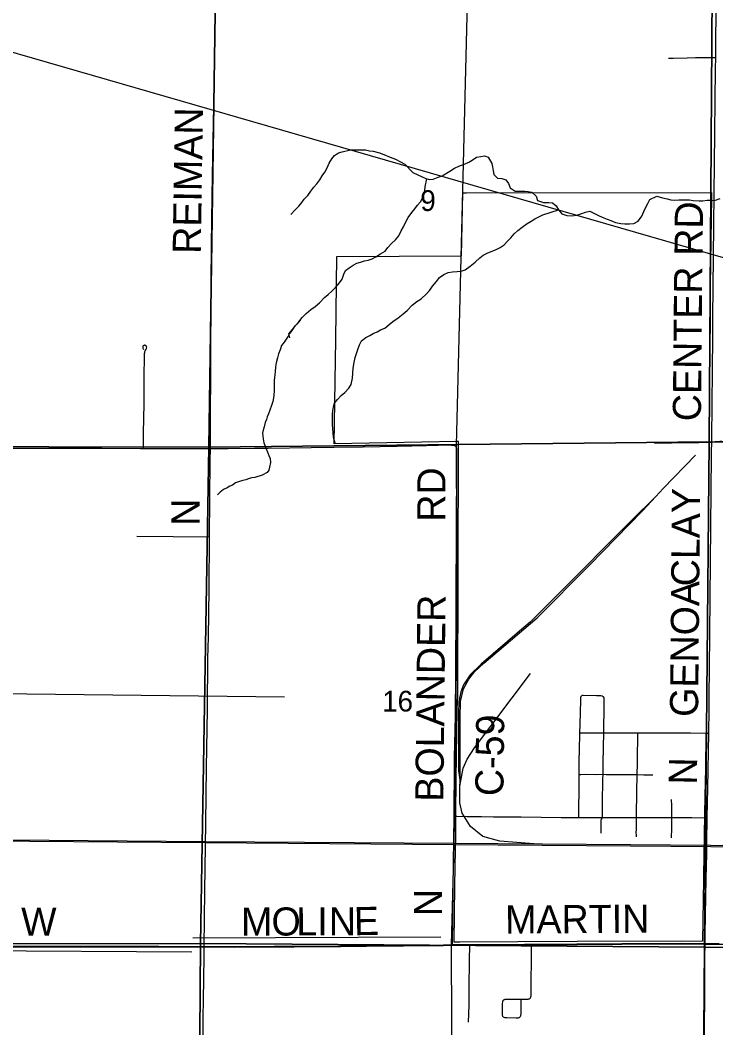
# Model space of a CAD drawing. Extents: x 0 to 34, y 0 to 22.
# Drawn here: x 6.257 to 7.662, y 17.233 to 19.268 of the extents above; entities that cross this region are included whole.
import ezdxf

# ---------------------------------------------------------------- set-up
doc = ezdxf.new("R2010")
doc.units = 0
for name, color, linetype in [('GM_X_City_Street', 7, 'Continuous'), ('GM_X_Corporation', 7, 'Continuous'), ('GM_X_County_Road', 7, 'Continuous'), ('GM_X_County_Road_Text', 7, 'Continuous'), ('GM_X_Interstate_Route', 7, 'Continuous'), ('GM_X_Minor_River', 7, 'Continuous'), ('GM_X_Rail_Line', 7, 'Continuous'), ('GM_X_Section', 7, 'Continuous'), ('GM_X_Section_Text', 7, 'Continuous'), ('GM_X_Township_Road', 7, 'Continuous'), ('GM_X_Township_Road_Text', 7, 'Continuous'), ('SH_Text', 7, 'Continuous')]:
    doc.layers.add(name, color=color, linetype=linetype)

msp = doc.modelspace()

# ---------------------------------------------------------------- linework, layer by layer
at = {"layer": 'GM_X_City_Street'}
for points in [[(7.5379, 18.4138), (7.5471, 18.4143), (7.5718, 18.4148), (7.6271, 18.4153), (7.6462, 18.4158), (7.6532, 18.4161)], [(7.385, 17.6579), (7.3851, 17.667), (7.3853, 17.7216), (7.3855, 17.745), (7.3857, 17.7742), (7.3861, 17.7928), (7.3871, 17.8289), (7.3876, 17.8454), (7.3888, 17.8949), (7.3892, 17.9014), (7.3894, 17.9023), (7.3903, 17.9036), (7.3909, 17.9042)], [(7.3909, 17.9042), (7.3921, 17.9048), (7.3938, 17.9051), (7.4205, 17.9045), (7.4291, 17.9041), (7.4319, 17.9035), (7.434, 17.9023)], [(7.4301, 17.6259), (7.4301, 17.6342), (7.43, 17.6402), (7.43, 17.6489), (7.4302, 17.6524), (7.431, 17.6546), (7.4324, 17.6579), (7.4324, 17.6634), (7.4324, 17.672), (7.4329, 17.6868), (7.4335, 17.7354), (7.4338, 17.7451), (7.4341, 17.7711), (7.4347, 17.7957), (7.435, 17.8077), (7.4352, 17.821), (7.4352, 17.829), (7.4353, 17.8445), (7.436, 17.8706), (7.436, 17.8769), (7.4363, 17.8894), (7.4363, 17.8956), (7.4358, 17.8991), (7.4353, 17.9007), (7.434, 17.9023)], [(7.3871, 17.8289), (7.392, 17.8289), (7.3951, 17.829), (7.4107, 17.8288), (7.4352, 17.829), (7.4606, 17.8288), (7.5042, 17.8289), (7.5137, 17.8289), (7.6106, 17.8287), (7.6418, 17.8285), (7.6472, 17.8285)], [(7.5011, 17.6188), (7.5011, 17.6219), (7.501, 17.6278), (7.5011, 17.6337), (7.5013, 17.6367), (7.5014, 17.6429), (7.5013, 17.658), (7.5014, 17.6605), (7.5015, 17.6708), (7.5017, 17.6739), (7.5016, 17.677), (7.5017, 17.6801), (7.502, 17.6915), (7.5021, 17.7081), (7.5023, 17.7211), (7.5027, 17.7324), (7.503, 17.7445), (7.5033, 17.7667), (7.5034, 17.7829), (7.5037, 17.7948), (7.5039, 17.8069), (7.5042, 17.8195), (7.5042, 17.8289)], [(7.3855, 17.745), (7.389, 17.745), (7.3991, 17.7451), (7.4203, 17.7449), (7.4338, 17.7451), (7.4401, 17.7446), (7.4546, 17.7444), (7.4655, 17.7446), (7.4791, 17.7444), (7.4946, 17.7444), (7.503, 17.7445), (7.5161, 17.7442), (7.5346, 17.7438)], [(7.5723, 17.6169), (7.5724, 17.6355), (7.5727, 17.6579), (7.5727, 17.6634), (7.5726, 17.682), (7.5723, 17.6943)], [(7.1329, 17.6604), (7.1386, 17.6603), (7.1597, 17.6599), (7.1882, 17.6597), (7.2129, 17.6594), (7.2346, 17.6592), (7.2688, 17.6589), (7.3494, 17.658), (7.3774, 17.6579), (7.385, 17.6579), (7.4324, 17.6579), (7.5013, 17.658), (7.5201, 17.6579), (7.5512, 17.6579), (7.5727, 17.6579), (7.6132, 17.6577), (7.6409, 17.6573), (7.6443, 17.6572)]]:
    msp.add_lwpolyline(points, dxfattribs=at)
at = {"layer": 'GM_X_Corporation'}
msp.add_lwpolyline([(7.1415, 18.417), (7.1409, 18.417), (7.1384, 18.4169), (6.9975, 18.4142), (6.891, 18.4123), (6.8941, 18.6234), (6.8966, 18.7909), (7.148, 18.7918), (7.1506, 18.9195), (7.1582, 18.9196), (7.6531, 18.9202), (7.653, 18.9097), (7.6516, 18.8246), (7.6504, 18.7301), (7.6499, 18.6685), (7.6493, 18.6019), (7.6489, 18.544), (7.648, 18.436), (7.6478, 18.4181), (7.6478, 18.4125), (7.6475, 18.3869), (7.6454, 18.1634), (7.643, 17.9082), (7.643, 17.9056), (7.6428, 17.8895), (7.6418, 17.8336), (7.6417, 17.8241), (7.6413, 17.8017), (7.6409, 17.7795), (7.6404, 17.7573), (7.6394, 17.7012), (7.6388, 17.6639), (7.6387, 17.6582), (7.6386, 17.6525), (7.6382, 17.633), (7.6379, 17.6139), (7.6374, 17.5893), (7.6364, 17.5325), (7.6344, 17.4083), (7.3813, 17.4073), (7.2621, 17.4069), (7.1448, 17.4059), (7.1334, 17.4058), (7.1345, 17.5199), (7.1359, 17.5933), (7.1363, 17.6151), (7.1366, 17.6571), (7.1366, 17.6647), (7.1371, 17.7348), (7.1394, 17.8768), (7.1403, 17.9034), (7.1413, 18.1554), (7.1423, 18.4113), (7.1422, 18.417)], close=True, dxfattribs=at)
at = {"layer": 'GM_X_County_Road'}
msp.add_line((7.13, 17.3998), (7.1649, 17.4001), dxfattribs=at)
for points in [[(7.6615, 19.1928), (7.6618, 19.2257), (7.663, 19.3406), (7.6641, 19.424)], [(7.6556, 18.6674), (7.657, 18.7904), (7.6583, 18.918), (7.6589, 18.977), (7.6612, 19.1697), (7.6615, 19.1928)], [(7.6532, 18.4161), (7.6532, 18.4267), (7.6539, 18.4889), (7.6545, 18.5635), (7.6552, 18.6256), (7.6553, 18.6474), (7.6556, 18.6674)], [(7.1329, 17.6604), (7.1331, 17.6793), (7.1336, 17.7476), (7.1341, 17.7787), (7.1357, 17.8625), (7.1368, 17.9526), (7.1368, 17.9836), (7.1367, 18.0054), (7.1372, 18.0271), (7.1372, 18.0395), (7.1376, 18.0985), (7.1376, 18.1172), (7.1379, 18.2228), (7.1386, 18.3905), (7.1385, 18.3987), (7.1384, 18.4013), (7.1383, 18.4024), (7.1381, 18.4042), (7.1378, 18.4051), (7.1376, 18.4058), (7.137, 18.4067)], [(7.6483, 17.9044), (7.6489, 17.9574), (7.653, 18.3894), (7.6531, 18.3962), (7.6532, 18.4161)], [(7.6472, 17.8285), (7.648, 17.8766), (7.6483, 17.9004), (7.6483, 17.9044)], [(7.6443, 17.6572), (7.6443, 17.6592), (7.6448, 17.6871), (7.6454, 17.7181), (7.6472, 17.8285)], [(7.13, 17.3998), (7.1301, 17.4128), (7.1303, 17.447), (7.1312, 17.5275), (7.1318, 17.5523), (7.1316, 17.5678), (7.1325, 17.6112), (7.1329, 17.6604)], [(7.6402, 17.4023), (7.6403, 17.4231), (7.6421, 17.5349), (7.6432, 17.5846), (7.6436, 17.6157), (7.6443, 17.6499), (7.6443, 17.6572)], [(5.8898, 17.4002), (5.9248, 17.3997), (5.9621, 17.3993), (6.0584, 17.3982), (6.1734, 17.397), (6.2324, 17.3969), (6.2728, 17.3967), (6.3195, 17.3967), (6.3599, 17.3969), (6.3971, 17.3968), (6.4904, 17.397), (6.537, 17.3967), (6.6147, 17.3964), (6.6286, 17.3964)], [(6.6286, 17.3964), (6.6893, 17.3963), (6.77, 17.3966), (6.8104, 17.3969), (6.8415, 17.3971), (6.9037, 17.3975), (6.9565, 17.3979), (7.0031, 17.3986), (7.031, 17.3989), (7.1117, 17.3997), (7.13, 17.3998)], [(7.1649, 17.4001), (7.1819, 17.4002), (7.2224, 17.4005), (7.2754, 17.4009), (7.2892, 17.401)], [(7.2892, 17.401), (7.3814, 17.4014), (7.4718, 17.4022), (7.5933, 17.4026), (7.6402, 17.4023)], [(7.6367, 17.065), (7.6366, 17.0726), (7.6373, 17.1192), (7.6377, 17.1626), (7.6387, 17.2186), (7.6392, 17.3115), (7.6396, 17.3767), (7.6402, 17.4023)], [(7.6402, 17.4023), (7.6683, 17.4021), (7.7243, 17.4019), (7.8426, 17.4016), (7.908, 17.4013), (7.9796, 17.4005), (8.0792, 17.3999), (8.1321, 17.399), (8.266, 17.3978), (8.3189, 17.3974), (8.4403, 17.3965), (8.4714, 17.3958), (8.4806, 17.3953), (8.4898, 17.3941), (8.4989, 17.3923), (8.511, 17.3893), (8.5888, 17.3671), (8.6307, 17.3552), (8.6461, 17.3509)]]:
    msp.add_lwpolyline(points, dxfattribs=at)
at = {"layer": 'GM_X_Interstate_Route'}
for points in [[(6.2322, 17.3975), (6.2726, 17.3973), (6.3192, 17.3973), (6.3596, 17.3974), (6.3969, 17.3974), (6.4902, 17.3975), (6.5368, 17.3973), (6.6145, 17.397), (6.6284, 17.397), (6.6891, 17.3968), (6.7698, 17.3972), (6.8102, 17.3975), (6.8413, 17.3976), (6.9034, 17.3981), (6.9563, 17.3985), (7.0029, 17.3992), (7.0308, 17.3994), (7.1114, 17.4002), (7.1298, 17.4004), (7.1647, 17.4006), (7.1817, 17.4007), (7.2222, 17.401), (7.2752, 17.4014), (7.289, 17.4015), (7.3812, 17.402), (7.4715, 17.4028), (7.5931, 17.4031), (7.6399, 17.4028), (7.6681, 17.4026)], [(7.6681, 17.4026), (7.6399, 17.4028), (7.5931, 17.4031), (7.4715, 17.4028), (7.3812, 17.402), (7.289, 17.4015), (7.2752, 17.4014), (7.2222, 17.401), (7.1817, 17.4007), (7.1647, 17.4006), (7.1298, 17.4004), (7.1114, 17.4002), (7.0308, 17.3994), (7.0029, 17.3992), (6.9563, 17.3985), (6.9034, 17.3981), (6.8413, 17.3976), (6.8102, 17.3975), (6.7698, 17.3972), (6.6891, 17.3968), (6.6284, 17.397), (6.6145, 17.397), (6.5368, 17.3973), (6.4902, 17.3975), (6.3969, 17.3974), (6.3596, 17.3974), (6.3192, 17.3973), (6.2726, 17.3973), (6.2322, 17.3975)]]:
    msp.add_lwpolyline(points, dxfattribs=at)
at = {"layer": 'GM_X_Minor_River'}
for points in [[(6.8037, 18.8754), (6.8125, 18.8849), (6.8193, 18.8924), (6.8258, 18.8996), (6.8304, 18.9068), (6.838, 18.9143), (6.8441, 18.923), (6.8502, 18.9306), (6.8559, 18.9378), (6.862, 18.9457), (6.867, 18.9536), (6.872, 18.9608), (6.8769, 18.9699), (6.8808, 18.979), (6.8861, 18.9877), (6.8914, 18.9949), (6.8994, 19.0002), (6.9074, 19.002), (6.9241, 19.0061), (6.9381, 19.0064), (6.9464, 19.0064), (6.9544, 19.006), (6.9623, 19.0044), (6.9695, 19.0032), (6.9828, 19.0001), (6.9911, 18.997), (7.0043, 18.9913), (7.0149, 18.9871), (7.0247, 18.9817), (7.0334, 18.9771), (7.0496, 18.9607), (7.0599, 18.9557), (7.0674, 18.9526), (7.0757, 18.948), (7.0829, 18.9461), (7.0905, 18.9472), (7.1011, 18.951), (7.1091, 18.954), (7.1243, 18.9634), (7.1342, 18.969), (7.1425, 18.9731), (7.1554, 18.978), (7.1627, 18.981), (7.1699, 18.9855), (7.1782, 18.9912), (7.1873, 18.993), (7.1945, 18.9941), (7.2017, 18.9914), (7.2096, 18.9789), (7.2107, 18.9717), (7.2118, 18.9637), (7.2133, 18.9561), (7.2205, 18.9488), (7.2292, 18.948), (7.2375, 18.9457), (7.2431, 18.9381), (7.2461, 18.9297), (7.2563, 18.9229), (7.2643, 18.9228), (7.2757, 18.9228), (7.2829, 18.9223), (7.29, 18.9208), (7.2991, 18.9128), (7.3017, 18.904), (7.3138, 18.8998), (7.3244, 18.8998), (7.3316, 18.899), (7.3392, 18.8928), (7.344, 18.8852), (7.3508, 18.8769), (7.3607, 18.8738), (7.3705, 18.873), (7.3811, 18.8744), (7.391, 18.8774), (7.3982, 18.8804), (7.4073, 18.8823), (7.4164, 18.8773), (7.4247, 18.8734), (7.4323, 18.87), (7.4421, 18.8665), (7.4493, 18.8635), (7.4591, 18.8592), (7.4697, 18.8573), (7.478, 18.8565), (7.4875, 18.8568), (7.4958, 18.8575), (7.5046, 18.862), (7.5122, 18.8723), (7.5164, 18.8817), (7.5195, 18.8893), (7.5245, 18.898), (7.5283, 18.9056), (7.5423, 18.9123), (7.5537, 18.9092), (7.5635, 18.9069), (7.5707, 18.9054), (7.5779, 18.9046), (7.587, 18.9049), (7.5976, 18.9052), (7.6086, 18.9052), (7.6158, 18.904)], [(6.8013, 18.6264), (6.7991, 18.6345), (6.8067, 18.6432), (6.8129, 18.6515), (6.8193, 18.659), (6.8266, 18.6673), (6.8342, 18.6757), (6.8441, 18.684), (6.8528, 18.6896), (6.8612, 18.6972), (6.8711, 18.7077), (6.8791, 18.7141), (6.8863, 18.7209), (6.8939, 18.7281), (6.9019, 18.7376), (6.9073, 18.7447), (6.9107, 18.755), (6.9138, 18.7622), (6.921, 18.7678), (6.929, 18.7731), (6.937, 18.7776), (6.9442, 18.7791), (6.9522, 18.7817), (6.9597, 18.7836), (6.9677, 18.7858), (6.9753, 18.7899), (6.9844, 18.796), (6.9936, 18.8016), (6.9996, 18.8088), (7.0065, 18.8167), (7.0149, 18.8246), (7.0214, 18.8326), (7.0263, 18.8424), (7.0309, 18.8508), (7.0348, 18.8595), (7.0405, 18.8693), (7.0477, 18.8795), (7.0538, 18.8871), (7.0592, 18.8942), (7.0653, 18.9014), (7.0691, 18.9086), (7.0718, 18.9162), (7.0737, 18.9242), (7.0749, 18.9317), (7.0782, 18.9474)], [(7.6158, 18.904), (7.6279, 18.9035), (7.6355, 18.9035), (7.6438, 18.9046), (7.6518, 18.9046), (7.659, 18.9042), (7.67, 18.9079)], [(6.8932, 18.4135), (6.8898, 18.4253), (6.8887, 18.4344), (6.888, 18.4431), (6.8873, 18.4507), (6.8873, 18.4598), (6.8878, 18.4716), (6.8885, 18.4792), (6.8893, 18.4875), (6.8917, 18.4947), (6.8974, 18.5019), (6.905, 18.5098), (6.9126, 18.5163), (6.9206, 18.5246), (6.9252, 18.5325), (6.9279, 18.5454), (6.9287, 18.5549), (6.9291, 18.5655), (6.9311, 18.5769), (6.933, 18.5871), (6.9388, 18.603), (6.9419, 18.6121), (6.9464, 18.6208), (6.9552, 18.6269), (6.9628, 18.6314), (6.97, 18.6355), (6.9776, 18.6385), (6.9848, 18.6426), (6.9932, 18.646), (7.0019, 18.6532), (7.0095, 18.6592), (7.0202, 18.6668), (7.0301, 18.6747), (7.0381, 18.6815), (7.0487, 18.6928), (7.0578, 18.6996), (7.0666, 18.7052), (7.0776, 18.7154), (7.0841, 18.723), (7.0898, 18.7309), (7.0978, 18.7404), (7.1039, 18.7483), (7.1123, 18.7547), (7.1214, 18.7585), (7.1301, 18.7599), (7.1392, 18.7603), (7.1476, 18.761), (7.1555, 18.7636), (7.1654, 18.7715), (7.1753, 18.7791), (7.1848, 18.7878), (7.192, 18.7934), (7.1996, 18.7972), (7.208, 18.8009), (7.2167, 18.8043), (7.2262, 18.8092), (7.2342, 18.8141), (7.2411, 18.8216), (7.2479, 18.8288), (7.2544, 18.8367), (7.2616, 18.8435), (7.2704, 18.8503), (7.2803, 18.8575), (7.2886, 18.8624), (7.2962, 18.8669), (7.3042, 18.871), (7.3125, 18.8748), (7.344, 18.8852)], [(6.8221, 18.6622), (6.8153, 18.6544), (6.8096, 18.6472), (6.8054, 18.6411), (6.8009, 18.6351), (6.7978, 18.6297), (6.7937, 18.6237), (6.7899, 18.618), (6.7849, 18.6111), (6.7819, 18.6024), (6.7785, 18.5944), (6.7762, 18.5864), (6.7747, 18.5788), (6.7732, 18.5724), (6.7728, 18.567), (6.7716, 18.5583), (6.7709, 18.5515), (6.7705, 18.5461), (6.7701, 18.5404), (6.7701, 18.5336), (6.7697, 18.5275), (6.7697, 18.5207), (6.7693, 18.5097), (6.7671, 18.4979), (6.764, 18.488), (6.7618, 18.4823), (6.7583, 18.4728), (6.7557, 18.4667), (6.7542, 18.4614), (6.7519, 18.4553), (6.7496, 18.447), (6.7473, 18.4398), (6.7462, 18.4337), (6.7466, 18.428), (6.7473, 18.4227), (6.7488, 18.4147), (6.7515, 18.4078), (6.7538, 18.4025), (6.7572, 18.3942), (6.7591, 18.3888), (6.7617, 18.3831), (6.7625, 18.3748), (6.7606, 18.3656), (6.7591, 18.3596), (6.7557, 18.3543), (6.7458, 18.3493), (6.731, 18.3448), (6.7242, 18.344), (6.7181, 18.3417), (6.7128, 18.3398), (6.7063, 18.3383), (6.6995, 18.3364), (6.6915, 18.3334), (6.6859, 18.3292), (6.6802, 18.3273), (6.6748, 18.3239), (6.6673, 18.3201), (6.6608, 18.3151), (6.6551, 18.3098)], [(6.7905, 17.9008), (6.1539, 17.9085), (6.1417, 17.9025), (6.1372, 17.6322)], [(7.1066, 17.4162), (6.6054, 17.4143)], [(6.6035, 17.3858), (4.8182, 17.3966)]]:
    msp.add_lwpolyline(points, dxfattribs=at)
at = {"layer": 'GM_X_Rail_Line'}
msp.add_line((7.145, 17.7213), (7.1451, 17.7301), dxfattribs=at)
for points in [[(7.2205, 20.9), (7.2191, 20.567), (7.2148, 20.5028), (7.2089, 20.4736), (7.1929, 20.443), (7.1768, 20.4036), (7.1637, 19.9147), (7.1622, 19.4128), (7.1374, 18.4088), (7.1389, 18.0601), (7.1325, 17.6042)], [(7.5401, 18.306), (7.5553, 18.3226), (7.6203, 18.3896)], [(7.5401, 18.306), (7.4904, 18.2573), (7.3414, 18.1068), (7.2865, 18.0522), (7.265, 18.0339), (7.1879, 17.9677), (7.1653, 17.9461), (7.1519, 17.9256), (7.1468, 17.9114), (7.1425, 17.8919), (7.1417, 17.8682), (7.1419, 17.7523), (7.1451, 17.7301)], [(7.1451, 17.7301), (7.1452, 17.7581), (7.1452, 17.8606), (7.1462, 17.8923), (7.1519, 17.9174), (7.1626, 17.9371), (7.1741, 17.9523), (7.1928, 17.9692), (7.3009, 18.061), (7.4068, 18.1677), (7.5134, 18.277), (7.5401, 18.306)], [(7.145, 17.7213), (7.1515, 17.7577), (7.1597, 17.7756), (7.1745, 17.7984), (7.2132, 17.8502), (7.2874, 17.9484)], [(7.2943, 17.6046), (7.2255, 17.6101), (7.1908, 17.6198), (7.1659, 17.6399), (7.1495, 17.6666), (7.145, 17.6874), (7.145, 17.7213)], [(4.7039, 17.6237), (5.1874, 17.6209), (5.6534, 17.6172), (5.9221, 17.6153), (6.6307, 17.6096), (7.1327, 17.6059), (7.4891, 17.603), (7.6513, 17.6017), (7.7461, 17.6007), (7.7732, 17.5996), (7.7996, 17.5979), (7.8317, 17.5948), (7.856, 17.5922), (7.8859, 17.5877), (7.9297, 17.5801), (7.9694, 17.5712), (8.019, 17.5585), (8.0883, 17.5388), (8.2893, 17.4822), (8.4661, 17.4324), (8.6481, 17.3808), (8.9, 17.3095)], [(4.7039, 17.6214), (5.1874, 17.6186), (5.6534, 17.6149), (5.9221, 17.613), (6.6307, 17.6073), (7.1327, 17.6036), (7.489, 17.6007), (7.6513, 17.5994), (7.7461, 17.5984), (7.7731, 17.5973), (7.7994, 17.5956), (7.8314, 17.5925), (7.8557, 17.5899), (7.8855, 17.5854), (7.9292, 17.5778), (7.9689, 17.569), (8.0184, 17.5563), (8.0876, 17.5366), (8.2886, 17.48), (8.4655, 17.4302), (8.6474, 17.3785), (8.9, 17.3071)], [(7.1325, 17.6042), (7.1272, 17.4005), (7.1287, 17.0765), (7.1229, 16.3878), (7.1287, 15.8668)]]:
    msp.add_lwpolyline(points, dxfattribs=at)
at = {"layer": 'GM_X_Section'}
for points in [[(5.6799, 19.4229), (6.6525, 19.4215), (6.6382, 18.4059), (5.6682, 18.408)], [(7.6545, 19.4258), (7.6481, 18.4165), (6.6382, 18.4059), (6.6525, 19.4215)], [(8.666, 19.4088), (8.6554, 18.3927), (7.6481, 18.4165), (7.6545, 19.4258)], [(5.6682, 18.408), (6.6382, 18.4059), (6.6213, 17.4032), (5.6487, 17.4026)], [(7.6481, 18.4165), (7.639, 17.3962), (6.6213, 17.4032), (6.6382, 18.4059)], [(8.6554, 18.3927), (8.6426, 17.3907), (7.639, 17.3962), (7.6481, 18.4165)], [(6.6213, 17.4032), (6.6138, 16.3837), (5.6285, 16.3977), (5.6487, 17.4026)], [(7.639, 17.3962), (7.6303, 16.3805), (6.6138, 16.3837), (6.6213, 17.4032)], [(7.639, 17.3962), (8.6426, 17.3907), (8.6324, 16.375), (7.6303, 16.3805)]]:
    msp.add_lwpolyline(points, close=True, dxfattribs=at)
at = {"layer": 'GM_X_Township_Road'}
msp.add_line((6.4923, 18.2257), (6.6392, 18.2248), dxfattribs=at)
for points in [[(6.641, 18.403), (6.6414, 18.4637), (6.6419, 18.5601), (6.6428, 18.7373), (6.6435, 18.8121), (6.644, 18.8648), (6.6455, 18.955), (6.649, 19.1653), (6.6493, 19.1819), (6.6531, 19.4163)], [(7.5661, 19.1913), (7.5751, 19.1914), (7.6034, 19.192), (7.6205, 19.1924), (7.6345, 19.1925), (7.6498, 19.1928), (7.6615, 19.1928)], [(6.506, 18.4032), (6.506, 18.4054), (6.5061, 18.4349), (6.507, 18.4931), (6.5075, 18.5423), (6.5081, 18.5946), (6.5084, 18.5972), (6.5086, 18.598), (6.5089, 18.599), (6.5095, 18.6004), (6.5105, 18.602), (6.5114, 18.6035), (6.512, 18.6048), (6.5122, 18.6057), (6.5123, 18.6065), (6.5124, 18.6074), (6.5122, 18.6082), (6.5118, 18.6093), (6.5111, 18.6102), (6.51, 18.6109), (6.5091, 18.6114), (6.5079, 18.6114), (6.5071, 18.6113), (6.5064, 18.611), (6.5056, 18.6104), (6.5049, 18.6096), (6.5046, 18.6089), (6.5045, 18.6082), (6.5044, 18.6073), (6.5045, 18.6064), (6.5046, 18.6054), (6.5051, 18.6046), (6.5062, 18.6032)], [(7.6532, 18.4161), (7.6573, 18.4167), (7.6604, 18.4171), (7.6631, 18.4173), (7.6662, 18.4175), (7.6695, 18.4176), (7.6739, 18.4176), (7.907, 18.4122), (8.0624, 18.4077), (8.1121, 18.4062), (8.2054, 18.4038), (8.2831, 18.4021), (8.3298, 18.4009), (8.4479, 18.3983), (8.5785, 18.3952), (8.6438, 18.3935), (8.6602, 18.3934)], [(5.6652, 18.4079), (5.7098, 18.4074), (5.7346, 18.4073), (5.7844, 18.4067), (5.8559, 18.4063), (5.9586, 18.4054), (6.0923, 18.4048), (6.2198, 18.4038), (6.3318, 18.4038), (6.422, 18.4036), (6.4997, 18.4032), (6.506, 18.4032)], [(6.506, 18.4032), (6.5899, 18.4029), (6.641, 18.403)], [(6.6392, 18.2248), (6.6409, 18.3798), (6.641, 18.403)], [(6.641, 18.403), (6.677, 18.4031), (6.7298, 18.4035), (6.7578, 18.4036), (6.8448, 18.4051), (6.8907, 18.4055)], [(6.8907, 18.4055), (6.9498, 18.4067), (7.0184, 18.408), (7.0775, 18.409), (7.1243, 18.4103), (7.128, 18.4101), (7.1305, 18.4099), (7.1317, 18.4098), (7.1325, 18.4096), (7.1339, 18.409), (7.1345, 18.4087), (7.1364, 18.4075), (7.137, 18.4067)], [(6.6286, 17.3964), (6.6297, 17.5095), (6.6317, 17.6462), (6.6334, 17.7581), (6.635, 17.8762), (6.636, 17.9788), (6.6369, 18.0223), (6.6385, 18.1186), (6.6392, 18.2248)], [(7.1625, 17.2448), (7.1632, 17.2789), (7.1633, 17.3097), (7.1643, 17.3733), (7.1648, 17.3969), (7.1649, 17.4001)], [(7.2678, 17.2896), (7.2677, 17.2794), (7.2675, 17.2616), (7.2673, 17.258), (7.2672, 17.2568), (7.2667, 17.2557), (7.2658, 17.2545), (7.2649, 17.2537), (7.2637, 17.2531), (7.2625, 17.2529), (7.2582, 17.2529), (7.2395, 17.253), (7.2358, 17.2532), (7.234, 17.2537), (7.2326, 17.2546), (7.2317, 17.2557), (7.2312, 17.2568), (7.2309, 17.2582), (7.2308, 17.2594), (7.2308, 17.2625), (7.2308, 17.2817), (7.2312, 17.2855), (7.2315, 17.2868), (7.2318, 17.2877), (7.2324, 17.2885), (7.233, 17.2891), (7.2337, 17.2896), (7.2345, 17.2902), (7.2354, 17.2905), (7.2361, 17.2907), (7.2376, 17.2909), (7.2407, 17.291), (7.2501, 17.291), (7.2654, 17.2908), (7.2779, 17.2909), (7.2814, 17.2909), (7.2828, 17.291), (7.2841, 17.2914), (7.2854, 17.2919), (7.2867, 17.2929), (7.2876, 17.294), (7.2881, 17.2953), (7.2885, 17.2984), (7.2885, 17.3111), (7.2886, 17.3326), (7.2892, 17.3637), (7.2892, 17.3979), (7.2892, 17.401)], [(6.6254, 17.0608), (6.6254, 17.0623), (6.6258, 17.1617), (6.6267, 17.255), (6.6271, 17.2891), (6.6283, 17.3762), (6.6286, 17.3964)]]:
    msp.add_lwpolyline(points, dxfattribs=at)
at = {"layer": 'SH_Text'}
msp.add_lwpolyline([(9.2181, 19.0346), (2.1904, 20.3744), (9.2181, 18.3428)], close=True, dxfattribs=at)

# ---------------------------------------------------------------- texts
at = {"layer": 'GM_X_County_Road_Text'}
for s, height, rotation, p in [('RD', 0.05682, 89.5063, (7.6348, 18.792)), ('CENTER', 0.05682, 89.4725, (7.6314, 18.4579)), ('RD', 0.05682, 90, (7.1156, 18.2552)), ('CLAY', 0.05682, 89.4955, (7.6281, 18.1245)), ('GENOA', 0.05682, 89.4133, (7.6256, 17.8608)), ('BOLANDER', 0.05682, 89.3708, (7.1114, 17.6895)), ('C-59', 0.05682, 89.3107, (7.2325, 17.7008)), ('N', 0.0568, 89.0456, (7.6231, 17.7239)), ('N', 0.0568, 90, (7.1089, 17.4585)), ('MARTIN', 0.05682, 0.3466, (7.2362, 17.4234)), ('W', 0.0568, 0, (6.2588, 17.4192)), ('M', 0.0568, 0.189, (6.7029, 17.4192)), ('O', 0.0568, 0.1877, (6.7645, 17.4194)), ('L', 0.0568, 0.1843, (6.8145, 17.4196)), ('I', 0.0568, 0.1901, (6.857, 17.4197)), ('N', 0.0568, 0.2177, (6.8804, 17.4198)), ('E', 0.0568, 1.125, (6.9314, 17.42))]:
    msp.add_text(s, height=height, rotation=rotation, dxfattribs=at).set_placement(p)
at = {"layer": 'GM_X_Section_Text'}
for s, height, p in [('9', 0.0419, (7.065, 18.8827)), ('16', 0.04186, (6.9879, 17.8719))]:
    msp.add_text(s, height=height, rotation=0, dxfattribs=at).set_placement(p)
at = {"layer": 'GM_X_Township_Road_Text'}
for s, height, rotation, p in [('REIMAN', 0.05682, 89.1302, (6.6216, 18.7958)), ('N', 0.0568, 90, (6.6191, 18.2468))]:
    msp.add_text(s, height=height, rotation=rotation, dxfattribs=at).set_placement(p)

doc.saveas('drawing.dxf')
